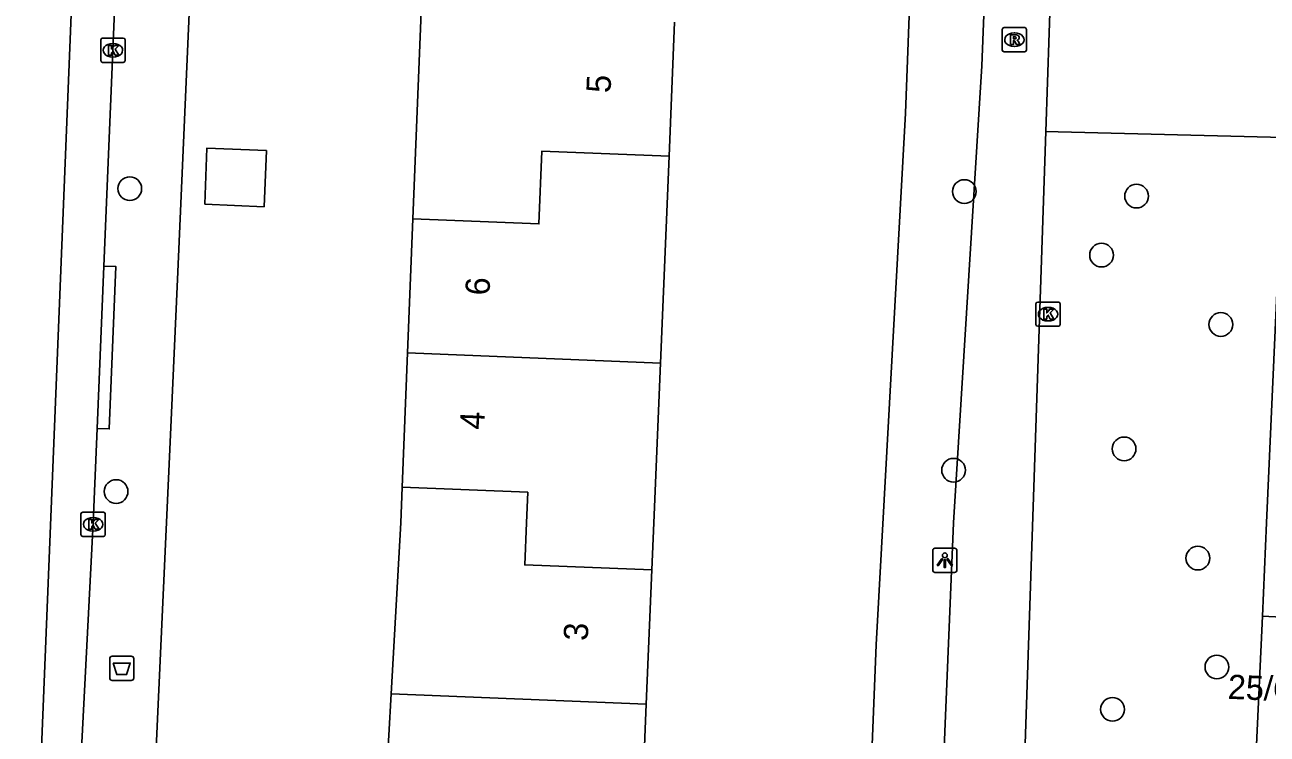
# Model space of a CAD drawing. Extents: x 160787 to 161428, y 386828 to 387483.
# Drawn here: x 160988.2 to 161039.4, y 386991.3 to 387020.5 of the extents above; entities that cross this region are included whole.
import ezdxf

# ---------------------------------------------------------------- set-up
doc = ezdxf.new("R2010")
doc.units = 0
for name, color, linetype in [('IMGEO_Afvalbak', 7, 'Continuous'), ('IMGEO_Boom', 7, 'Continuous'), ('IMGEO_Kolk', 7, 'Continuous'), ('IMGEO_Lichtpunt', 7, 'Continuous'), ('IMGEO_Muur', 7, 'Continuous'), ('IMGEO_Pand', 7, 'Continuous'), ('IMGEO_Pand_nummerreeks', 7, 'Continuous'), ('IMGEO_Rijbaan_lokaal_gesloten', 7, 'Continuous'), ('IMGEO_Rijbaan_lokaal_open', 7, 'Continuous'), ('IMGEO_Rioolput', 7, 'Continuous'), ('IMGEO_Voetpad_open', 7, 'Continuous')]:
    doc.layers.add(name, color=color, linetype=linetype)

msp = doc.modelspace()

# ---------------------------------------------------------------- linework, layer by layer
at = {"layer": 'IMGEO_Afvalbak'}
for p, q in [((160991.675, 386993.6), (160991.675, 386994.4)), ((160991.675, 386994.4), (160991.675, 386993.6)), ((160991.775, 386994.5), (160992.565, 386994.5)), ((160992.565, 386994.5), (160991.775, 386994.5)), ((160992.665, 386994.4), (160992.665, 386993.6)), ((160992.665, 386993.6), (160992.665, 386994.4)), ((160992.565, 386993.5), (160991.775, 386993.5)), ((160991.775, 386993.5), (160992.565, 386993.5))]:
    msp.add_line(p, q, dxfattribs=at)
msp.add_lwpolyline([(160991.818, 386994.214), (160992.522, 386994.214), (160992.373, 386993.744), (160991.967, 386993.744), (160991.818, 386994.214)], dxfattribs=at)
for centre, start, end in [((160991.775, 386994.4), 90, 180), ((160991.775, 386994.4), 90, 180), ((160992.565, 386994.4), 0, 90), ((160992.565, 386994.4), 360, 90), ((160991.775, 386993.6), 180, 270), ((160991.775, 386993.6), 180, 270), ((160992.565, 386993.6), 270, 0), ((160992.565, 386993.6), 270, 0)]:
    msp.add_arc(centre, 0.1, start, end, dxfattribs=at)
at = {"layer": 'IMGEO_Boom'}
for centre in [(160992.501, 387013.773), (161026.923, 387013.653), (161034.026, 387013.466), (161032.58, 387011.035), (161037.5, 387008.174), (161033.509, 387003.045), (161026.478, 387002.165), (160991.936, 387001.288), (161036.552, 386998.544), (161037.336, 386994.054), (161033.032, 386992.31)]:
    msp.add_circle(centre, 0.489, dxfattribs=at)
at = {"layer": 'IMGEO_Kolk'}
for p, q in [((160991.306, 387019.052), (160991.306, 387019.904)), ((160991.381, 387019.978), (160992.233, 387019.978)), ((160991.794, 387019.758), (160991.819, 387019.758)), ((160992.307, 387019.904), (160992.307, 387019.052)), ((160992.233, 387018.978), (160991.381, 387018.978)), ((160991.817, 387019.198), (160991.792, 387019.198)), ((161029.873, 387008.173), (161029.873, 387009.025)), ((161029.948, 387009.099), (161030.8, 387009.099)), ((161030.874, 387009.025), (161030.874, 387008.173)), ((161030.361, 387008.879), (161030.386, 387008.879)), ((161030.8, 387008.099), (161029.948, 387008.099)), ((161030.384, 387008.319), (161030.359, 387008.319)), ((160990.488, 386999.511), (160990.488, 387000.363)), ((160990.563, 387000.437), (160991.415, 387000.437)), ((160991.489, 387000.363), (160991.489, 386999.511)), ((160990.976, 387000.217), (160991.001, 387000.217)), ((160991.415, 386999.437), (160990.563, 386999.437)), ((160990.999, 386999.657), (160990.974, 386999.657))]:
    msp.add_line(p, q, dxfattribs=at)
for points in [[(160991.306, 387019.052), (160991.306, 387019.904)], [(160991.381, 387019.978), (160992.233, 387019.978)], [(160992.307, 387019.904), (160992.307, 387019.052)], [(160991.627, 387019.678), (160991.75, 387019.678), (160991.75, 387019.527), (160991.88, 387019.678), (160992.044, 387019.678), (160991.898, 387019.527), (160992.051, 387019.278), (160991.899, 387019.278), (160991.814, 387019.442), (160991.75, 387019.375), (160991.75, 387019.278), (160991.627, 387019.278), (160991.627, 387019.678)], [(160992.233, 387018.978), (160991.381, 387018.978)], [(161029.873, 387008.173), (161029.873, 387009.025)], [(161029.948, 387009.099), (161030.8, 387009.099)], [(161030.874, 387009.025), (161030.874, 387008.173)], [(161030.194, 387008.799), (161030.317, 387008.799), (161030.317, 387008.648), (161030.447, 387008.799), (161030.611, 387008.799), (161030.465, 387008.648), (161030.618, 387008.399), (161030.466, 387008.399), (161030.381, 387008.563), (161030.317, 387008.496), (161030.317, 387008.399), (161030.194, 387008.399), (161030.194, 387008.799)], [(161030.8, 387008.099), (161029.948, 387008.099)], [(160990.488, 386999.511), (160990.488, 387000.363)], [(160990.563, 387000.437), (160991.415, 387000.437)], [(160991.489, 387000.363), (160991.489, 386999.511)], [(160990.809, 387000.137), (160990.932, 387000.137), (160990.932, 386999.986), (160991.062, 387000.137), (160991.226, 387000.137), (160991.08, 386999.986), (160991.233, 386999.737), (160991.081, 386999.737), (160990.996, 386999.901), (160990.932, 386999.834), (160990.932, 386999.737), (160990.809, 386999.737), (160990.809, 387000.137)], [(160991.415, 386999.437), (160990.563, 386999.437)]]:
    msp.add_lwpolyline(points, dxfattribs=at)
for centre, start, end in [((160991.383, 387019.902), 91.552, 178.448), ((160991.383, 387019.902), 91.552, 178.448), ((160992.231, 387019.902), 1.552, 88.448), ((160992.231, 387019.902), 1.552, 88.448), ((160991.383, 387019.054), 181.552, 268.448), ((160991.383, 387019.054), 181.552, 268.448), ((160992.231, 387019.054), 271.552, 358.448), ((160992.231, 387019.054), 271.552, 358.448), ((161029.95, 387009.023), 91.552, 178.448), ((161029.95, 387009.023), 91.552, 178.448), ((161030.798, 387009.023), 1.552, 88.448), ((161030.798, 387009.023), 1.552, 88.448), ((161029.95, 387008.175), 181.552, 268.448), ((161029.95, 387008.175), 181.552, 268.448), ((161030.798, 387008.175), 271.552, 358.448), ((161030.798, 387008.175), 271.552, 358.448), ((160990.565, 387000.361), 91.552, 178.448), ((160990.565, 387000.361), 91.552, 178.448), ((160991.413, 387000.361), 1.552, 88.448), ((160991.413, 387000.361), 1.552, 88.448), ((160990.565, 386999.513), 181.552, 268.448), ((160990.565, 386999.513), 181.552, 268.448), ((160991.413, 386999.513), 271.552, 358.448), ((160991.413, 386999.513), 271.552, 358.448)]:
    msp.add_arc(centre, 0.0765, start, end, dxfattribs=at)
for centre, major_axis, ratio, start_param, end_param in [((160991.793, 387019.478), (-0.387, 0.002), 0.722429, 4.712389, 7.853982), ((160991.818, 387019.478), (-0.39, 0.002), 0.717154, 1.570796, 4.712389), ((161030.36, 387008.599), (-0.387, 0.002), 0.722429, 4.712389, 7.853982), ((161030.385, 387008.599), (-0.39, 0.002), 0.717154, 1.570796, 4.712389), ((160990.975, 386999.937), (-0.387, 0.002), 0.722429, 4.712389, 7.853982), ((160991, 386999.937), (-0.39, 0.002), 0.717154, 1.570796, 4.712389)]:
    msp.add_ellipse(centre, major_axis=major_axis, ratio=ratio, start_param=start_param, end_param=end_param, dxfattribs=at)
at = {"layer": 'IMGEO_Lichtpunt'}
for p, q in [((161025.616, 386998.858), (161025.616, 386998.051)), ((161025.616, 386998.858), (161025.616, 386998.051)), ((161026.518, 386998.953), (161025.71, 386998.953)), ((161026.518, 386998.953), (161025.71, 386998.953)), ((161026.612, 386998.051), (161026.612, 386998.858)), ((161026.612, 386998.051), (161026.612, 386998.858)), ((161025.71, 386997.957), (161026.518, 386997.957)), ((161025.71, 386997.957), (161026.518, 386997.957))]:
    msp.add_line(p, q, dxfattribs=at)
for points in [[(161025.99, 386998.522), (161026.029, 386998.494), (161025.841, 386998.232), (161025.803, 386998.259), (161025.99, 386998.522)], [(161026.092, 386998.474), (161026.139, 386998.474), (161026.139, 386998.152), (161026.092, 386998.152), (161026.092, 386998.474)], [(161026.202, 386998.494), (161026.24, 386998.521), (161026.427, 386998.259), (161026.388, 386998.231), (161026.202, 386998.494)]]:
    msp.add_lwpolyline(points, dxfattribs=at)
msp.add_circle((161026.115, 386998.656), 0.0994, dxfattribs=at)
for centre, start, end in [((161025.71, 386998.858), 90, 180), ((161025.71, 386998.858), 90, 180), ((161026.518, 386998.858), 0, 90), ((161026.518, 386998.858), 0, 90), ((161025.71, 386998.051), 180, 270), ((161025.71, 386998.051), 180, 270), ((161026.518, 386998.051), 270, 0), ((161026.518, 386998.051), 270, 360)]:
    msp.add_arc(centre, 0.0946, start, end, dxfattribs=at)
at = {"layer": 'IMGEO_Muur'}
msp.add_lwpolyline([(161024.495, 387016.889), (161023.284, 386994.966)], dxfattribs=at)
at = {"layer": 'IMGEO_Pand'}
for points in [[(161004.523, 387021.057), (161004.181, 387012.53)], [(161014.742, 387015.108), (161014.972, 387020.637)], [(161040.103, 387015.882), (161039.388, 387000), (161039.215, 386996.146)], [(160995.591, 387013.128), (160998.042, 387013.029), (160998.135, 387015.346), (160995.684, 387015.445), (160995.591, 387013.128)], [(161004.181, 387012.53), (161009.374, 387012.321), (161009.494, 387015.318), (161014.742, 387015.108)], [(161014.388, 387006.581), (161014.742, 387015.108)], [(161004.181, 387012.53), (161003.959, 387007)], [(161003.959, 387007), (161003.737, 387001.47)], [(161003.959, 387007), (161014.388, 387006.581)], [(161014.034, 386998.055), (161014.115, 387000), (161014.388, 387006.581)], [(161003.737, 387001.47), (161003.678, 387000), (161003.279, 386992.949)], [(161003.737, 387001.47), (161008.915, 387001.262), (161008.863, 387000), (161008.791, 386998.265), (161014.034, 386998.055)], [(161013.804, 386992.526), (161014.034, 386998.055)], [(161039.215, 386996.146), (161038.95, 386990.26)], [(161039.215, 386996.146), (161042.162, 386996.001)], [(161003.279, 386992.949), (161002.796, 386984.426)], [(161013.804, 386992.526), (161003.279, 386992.949)], [(161013.575, 386986.995), (161013.804, 386992.526)]]:
    msp.add_lwpolyline(points, dxfattribs=at)
at = {"layer": 'IMGEO_Rijbaan_lokaal_gesloten'}
for points in [[(160987.959, 386958.658), (160987.876, 386966.266), (160992.785, 387087.527)], [(160991.434, 387010.584), (160992.274, 387030.665), (160992.337, 387032.289)], [(160991.155, 387003.893), (160991.434, 387010.584)], [(160990.152, 386982.628), (160990.167, 386982.998), (160990.497, 386990.405), (160990.992, 387000), (160991.155, 387003.893)]]:
    msp.add_lwpolyline(points, dxfattribs=at)
at = {"layer": 'IMGEO_Rijbaan_lokaal_open'}
for points in [[(161025.273, 386971.165), (161026.468, 387000), (161027.643, 387018.839), (161028.797, 387048.228)], [(161030.488, 387022.25), (161030.281, 387016.134)], [(161029.414, 386990.476), (161030.281, 387016.134)]]:
    msp.add_lwpolyline(points, dxfattribs=at)
at = {"layer": 'IMGEO_Rioolput'}
for p, q in [((161028.485, 387019.487), (161028.485, 387020.339)), ((161028.56, 387020.413), (161029.412, 387020.413)), ((161029.486, 387020.339), (161029.486, 387019.487)), ((161028.973, 387020.193), (161028.998, 387020.193)), ((161029.412, 387019.413), (161028.56, 387019.413)), ((161028.996, 387019.633), (161028.971, 387019.633))]:
    msp.add_line(p, q, dxfattribs=at)
for points in [[(161028.485, 387019.487), (161028.485, 387020.339)], [(161028.56, 387020.413), (161029.412, 387020.413)], [(161029.486, 387020.339), (161029.486, 387019.487)], [(161029.074, 387020.111), (161028.822, 387020.113), (161028.822, 387019.713)], [(161028.822, 387019.713), (161028.946, 387019.713), (161028.946, 387019.875), (161028.957, 387019.875)], [(161029, 387020.032), (161028.946, 387020.032), (161028.946, 387019.951)], [(161028.946, 387019.951), (161028.998, 387019.951)], [(161029.004, 387019.846), (161029.075, 387019.713), (161029.215, 387019.713), (161029.15, 387019.839)], [(161029.412, 387019.413), (161028.56, 387019.413)]]:
    msp.add_lwpolyline(points, dxfattribs=at)
for centre, radius, start, end in [((161028.562, 387020.337), 0.0765, 91.552, 178.448), ((161028.562, 387020.337), 0.0765, 91.552, 178.448), ((161029.41, 387020.337), 0.0765, 1.552, 88.448), ((161029.41, 387020.337), 0.0765, 1.552, 88.448), ((161028.956, 387019.822), 0.0533, 26.0293, 88.6989), ((161028.982, 387020.14), 0.19, 274.7715, 282.9687), ((161029.006, 387019.936), 0.0964, 77.0061, 93.1865), ((161029.02, 387019.993), 0.0378, 276.6634, 79.6772), ((161029.073, 387020.001), 0.109, 350.3612, 89.416), ((161029.071, 387020.001), 0.112, 277.5842, 350.9817), ((161029.055, 387019.786), 0.108, 29.5134, 73.7905), ((161028.562, 387019.489), 0.0765, 181.552, 268.448), ((161028.562, 387019.489), 0.0765, 181.552, 268.448), ((161029.41, 387019.489), 0.0765, 271.552, 358.448), ((161029.41, 387019.489), 0.0765, 271.552, 358.448)]:
    msp.add_arc(centre, radius, start, end, dxfattribs=at)
for centre, major_axis, ratio, start_param, end_param in [((161028.972, 387019.913), (-0.387, 0.002), 0.722429, 4.712389, 7.853982), ((161028.997, 387019.913), (-0.39, 0.002), 0.717154, 1.570796, 4.712389)]:
    msp.add_ellipse(centre, major_axis=major_axis, ratio=ratio, start_param=start_param, end_param=end_param, dxfattribs=at)
at = {"layer": 'IMGEO_Voetpad_open'}
for points in [[(161025.649, 387048.545), (161025.515, 387045.28), (161024.73, 387023.1), (161024.495, 387016.889), (161023.284, 386994.966), (161023.031, 386988.788), (161022.276, 386971.392)], [(160992.771, 386972.563), (160993.114, 386978.998), (160993.202, 386982.303), (160994.189, 387003.929), (160994.481, 387010.339), (160995.847, 387041.376)], [(161030.281, 387016.134), (161030.788, 387016.117), (161040.103, 387015.882)], [(160991.155, 387003.893), (160991.654, 387003.872), (160991.933, 387010.563), (160991.434, 387010.584)]]:
    msp.add_lwpolyline(points, dxfattribs=at)

# ---------------------------------------------------------------- texts
at = {"layer": 'IMGEO_Pand_nummerreeks'}
for s, rotation, p in [('5', 87.6217, (161012.328, 387017.703)), ('6', 87.7011, (161007.337, 387009.359)), ('4', 87.7011, (161007.115, 387003.829)), ('3', 87.6207, (161011.39, 386995.12)), ('25/G01', 357.594, (161037.771, 386992.746))]:
    msp.add_text(s, height=1, rotation=rotation, dxfattribs=at).set_placement(p)

doc.saveas('drawing.dxf')
